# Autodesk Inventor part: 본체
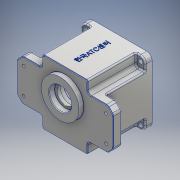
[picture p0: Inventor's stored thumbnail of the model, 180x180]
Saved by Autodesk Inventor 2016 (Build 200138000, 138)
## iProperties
Created: 2017-01
Part Number: 본체
Material: 알루미늄 6061
Document SubType Name: Modeling
Designer: Owner
Mass: 877.062 g
Surface Area: 764.541 cm^2
Volume: 324.838 cm^3
Density: 2.7 g/cm^3
Appearance: 알루미늄 - 평지
Author: Owner
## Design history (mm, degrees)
sketch "스케치3"
  geometry: 1 further point
sketch "스케치4"
  geometry: L1 (-47, -30)-(-47, 30); L2 (47, 30)-(47, -30); L3 (47, -30)-(-47, 30); L4 (-47, -30)-(47, 30); L5 (-33, -47)-(33, -47); L6 (33, 47)-(-33, 47); L7 (-33, -47)-(33, 47); L8 (33, -47)-(-33, 47); L9 (33, -47)-(33, -30); L10 (33, 30)-(33, 47); L11 (-47, 30)-(-33, 30); L12 (33, 30)-(47, 30); L13 (-33, 47)-(-33, 30); L14 (-33, -30)-(-33, -47); L15 (47, -30)-(33, -30); L16 (-33, -30)-(-47, -30); 1 further point
  constraints: 32 end point, 10 parallel, 4 equal length, 4 midpoint, 4 perpendicular, 3 horizontal
  dimensions: "d4" = 60 distance of L1.start L1.end; "d5" = 66 distance of L6.start L6.end; "d6" = 94 distance of L2.end L1.start; "d7" = 94 distance of L6.end L5.start
extrude "돌출2" new body sketch "스케치4" distance "d8" = 80; taper "d9" = 0 deg
sketch "스케치5"
  geometry: L1 (47, 47)-(-47, 47); L2 (-47, 47)-(-47, -47); L3 (-47, -47)-(47, -47); L4 (47, -47)-(47, 47); L5 (47, 47)-(-47, -47); L6 (-47, 47)-(47, -47); 3 further points
  constraints: 12 end point, 2 midpoint, 2 parallel, 1 horizontal, 1 horizontal alignment, 1 perpendicular, 1 vertical alignment
extrude "돌출3" join sketch "스케치5" distance "d10" = 10; taper "d11" = 0 deg
sketch "스케치6"
  geometry: L1 (-62, -30)-(62, -30); L2 (70, -22)-(70, 22); L3 (62, 30)-(-62, 30); L4 (-70, 22)-(-70, -22); L5 (-70, -30)-(70, 30); L6 (70, -30)-(-70, 30); L7 (-62, 30)-(-70, 22); L8 (-70, -22)-(-62, -30); L9 (62, -30)-(70, -22); L10 (62, 30)-(70, 22); 2 further points
  constraints: 20 end point, 8 point on line, 2 midpoint, 2 parallel, 1 horizontal, 1 horizontal alignment, 1 perpendicular
  dimensions: "d12" = 140 distance of L5.end L6.end; "d13" = 8 distance of L3.end L6.end; "d14" = 8 distance of L4.start L6.end (= d13); "d15" = 8 distance of L4.end L5.start (= d13); "d16" = 8 distance of L1.start L5.start (= d15); "d17" = 8 distance of L1.end L6.start (= d13); "d18" = 8 distance of L2.start L6.start (= d17); "d19" = 8 distance of L3.start L5.end (= d13); "d20" = 8 distance of L2.end L5.end (= d19)
extrude "돌출4" join sketch "스케치6" distance "d21" = 13; taper "d22" = 0 deg
sketch "스케치7"
  geometry: C1 r 27.5 at (0, 11); 1 further point
  constraints: 1 centre point, 1 vertical alignment
  dimensions: "d23" = 11 distance of C1.centre point (0, 0); "d24" = 55 diameter of C1
extrude "돌출5" join sketch "스케치7" distance "d25" = 7; taper "d26" = 0 deg
sketch "스케치9"
  geometry: C1 r 43 at (0, 0); 1 further point
  constraints: 1 centre point, 1 coincident
  dimensions: "d33" = 86 diameter of C1
extrude "돌출6" cut sketch "스케치9" distance "d34" = 9; taper "d35" = 0 deg
sketch "스케치10"
  geometry: C1 r 40 at (0, 0); 1 further point
  constraints: 1 centre point, 1 coincident
  dimensions: "d36" = 80 diameter of C1
extrude "돌출7" cut sketch "스케치10" distance "d37" = 62; taper "d38" = 0 deg
sketch "스케치11"
  geometry: C1 r 27.5 at (0, 0) reference; C2 r 16 at (0, 0); 1 further point
  constraints: 1 centre point, 1 coincident
  dimensions: "d39" = 32 diameter of C2
extrude "돌출8" cut sketch "스케치11" distance "d40" = 8; taper "d41" = 0 deg
sketch "스케치12"
  geometry: C1 r 16 at (0, 0) reference; C2 r 12.5 at (0, 0); 1 further point
  constraints: 1 centre point, 1 coincident
  dimensions: "d42" = 25 diameter of C2
extrude "돌출9" cut sketch "스케치12" distance "d43" = 9; taper "d44" = 0 deg
sketch "스케치15"
  geometry: C1 r 12.5 at (0, -11) reference; C2 r 21 at (0, -11); 1 further point
  constraints: 1 centre point, 1 coincident
  dimensions: "d48" = 42 diameter of C2
extrude "돌출11" join sketch "스케치15" distance "d49" = 7; taper "d50" = 0 deg
sketch "스케치16"
  geometry: C1 r 21 at (0, 0) reference; C2 r 17.5 at (0, 0); 1 further point
  constraints: 1 centre point, 1 coincident
  dimensions: "d51" = 35 diameter of C2
extrude "돌출12" cut sketch "스케치16" distance "d52" = 10; taper "d53" = 0 deg
sketch "스케치17"
  geometry: A1 r 36 centre (0, 0) between (35.778, -3.995) and (-34.366, -10.722); A2 r 4 centre (-36, 0) between (-35.852, -3.997) and (-35.852, 3.997); A3 r 4 centre (36, 0) between (35.852, 3.997) and (35.852, -3.997); A4 r 40 centre (0, 0) between (39.148, -8.214) and (39.148, 8.214) reference; A5 r 3.5 centre (35.722, -7.495) between (39.148, -8.214) and (35.778, -3.995); A6 r 3.5 centre (35.722, 7.495) between (35.778, 3.995) and (39.148, 8.214); A7 r 3.5 centre (-35.722, -7.495) between (-35.778, -3.995) and (-39.148, -8.214); A8 r 3.5 centre (-35.722, 7.495) between (-39.148, 8.214) and (-35.778, 3.995); 1 further point
  constraints: 27 point on circle, 8 tangent, 7 centre point, 2 horizontal alignment, 1 coincident
  dimensions: "d54" = 72 diameter of A1; "d55" = 8 diameter of A2; "d56" = 8 diameter of A3; "d57" = 7 diameter of A5; "d58" = 7 diameter of A6; "d59" = 7 diameter of A7; "d60" = 7 diameter of A8
extrude "돌출13" join sketch "스케치17" stored distance "d61" = 7; taper "d62" = 0 deg
sketch "스케치18"
  geometry: A1 r 15 centre (0, 20) between (8.978, 7.984) and (-8.978, 7.984); A2 r 21 centre (0, -11) between (-8.978, 7.984) and (8.978, 7.984) reference; 1 further point
  constraints: 4 point on circle, 1 centre point, 1 vertical alignment
  dimensions: "d63" = 20 distance of A1.centre point (0, 0); "d64" = 30 diameter of A1
extrude "돌출14" join sketch "스케치18" distance "d65" = 7; taper "d66" = 0 deg
sketch "스케치19"
  geometry: C1 r 11 at (0, 20); A1 r 15 centre (0, 20) between (8.978, 7.984) and (-8.978, 7.984) reference; 1 further point
  constraints: 1 centre point, 1 coincident
  dimensions: "d128" = 22 diameter of C1
extrude "돌출15" cut sketch "스케치19" distance "d68" = 7; taper "d69" = 0 deg
sketch "스케치20"
  geometry: C1 r 11 at (0, 0) reference; C2 r 9.5 at (0, 0); 1 further point
  constraints: 1 centre point, 1 coincident
  dimensions: "d70" = 19 diameter of C2
extrude "돌출16" cut sketch "스케치20" distance "d71" = 1; taper "d72" = 0 deg
fillet "모깎기1" dims "d73" = 8
sketch "스케치21"
  geometry: L1 (-40, -40)-(40, -40); L2 (40, -40)-(40, 40); L3 (40, 40)-(-40, 40); L4 (-40, 40)-(-40, -40); L5 (-40, -40)-(40, 40); L6 (40, -40)-(-40, 40); 5 further points
  constraints: 12 end point, 4 coincident, 2 midpoint, 2 parallel, 1 horizontal, 1 perpendicular
  dimensions: "d75" = 80 distance of L2.end L3.end; "d76" = 80 distance of L1.end L2.end
hole "구멍1" sketch "스케치21" at (40, 40), (40, -40), (-40, -40), (-40, 40) diameter "d77" = 7; stored, may be unused: countersink angle "d81" = 90 deg, drill point angle "d83" = 118 deg; dims "d78" = 6, "d79" = 10, "d80" = 4, "d82" = 8
sketch "스케치22"
  geometry: A1 r 4 centre (36, 0) between (35.852, 3.997) and (35.852, -3.997) reference; 2 further points
  constraints: 1 coincident
hole "구멍2" sketch "스케치22" at (36, 0) diameter "d84" = 3.242; stored, may be unused: countersink angle "d88" = 90 deg, drill point angle "d90" = 118 deg; dims "d85" = 7, "d86" = 10, "d87" = 4, "d89" = 9
chamfer "모따기1" distance "d91" = 1; stored, may be unused: second distance "d92" = 2, angle "d93" = 45 deg
fillet "모깎기3" dims "d94" = 0.3
fillet "모깎기4" dims "d95" = 2
fillet "모깎기5" dims "d96" = 0.3
chamfer "모따기2" distance "d97" = 1; stored, may be unused: second distance "d98" = 2, angle "d99" = 45 deg
sketch "스케치23"
  geometry: L1 (-33, -47)-(-33, -30) reference; L2 (33, -47)-(-33, -47) reference; L3 (33, -30)-(33, -47) reference; L4 (33, -30)-(62, -30) reference; L5 (62, -30)-(70, -22) reference; L6 (70, -22)-(70, 22) reference; L7 (70, 22)-(62, 30) reference; L8 (33, 30)-(62, 30) reference; L9 (33, 47)-(33, 30) reference; L10 (-33, 47)-(33, 47) reference; L11 (-33, 30)-(-33, 47) reference; L12 (-33, 30)-(-62, 30) reference; L13 (-62, 30)-(-70, 22) reference; L14 (-70, 22)-(-70, -22) reference; L15 (-70, -22)-(-62, -30) reference; L16 (-33, -30)-(-62, -30) reference; L17 (-61.586, 29)-(-32, 29); L18 (-32, 29)-(-32, 46); L19 (-32, 46)-(32, 46); L20 (32, 46)-(32, 29); L21 (32, 29)-(61.586, 29); L22 (61.586, 29)-(69, 21.586); L23 (69, 21.586)-(69, -21.586); L24 (69, -21.586)-(61.586, -29); L25 (61.586, -29)-(32, -29); L26 (32, -29)-(32, -46); L27 (32, -46)-(-32, -46); L28 (-32, -46)-(-32, -29); L29 (-32, -29)-(-61.586, -29); L30 (-61.586, -29)-(-69, -21.586); L31 (-69, -21.586)-(-69, 21.586); L32 (-69, 21.586)-(-61.586, 29); C1 r 27.8 at (0, 11) reference; 1 further point
  constraints: 32 end point, 15 other
  dimensions: "d100" = 1 distance between parallel lines of L12 L17
extrude "돌출17" cut sketch "스케치23" distance "d101" = 1; taper "d102" = 0 deg
fillet "모깎기6" dims "d103" = 5
fillet "모깎기7" dims "d104" = 5
fillet "모깎기8" dims "d105" = 5
fillet "모깎기9" dims "d106" = 2
fillet "모깎기11" dims "d108" = 2
sketch "스케치24"
  geometry: 2 further points
  dimensions: "d109" = 19 vertical distance of point (0, 0) point (60, -19); "d110" = 60 horizontal distance of point (0, 0) point (60, -19)
hole "구멍3" sketch "스케치24" at (60, -19) diameter "d111" = 4; stored, may be unused: countersink angle "d115" = 90 deg, drill point angle "d117" = 118 deg; dims "d112" = 4, "d113" = 10, "d114" = 4, "d116" = 9
fillet "모깎기13" dims "d119" = 2
fillet "모깎기14" dims "d120" = 2
fillet "모깎기15" dims "d121" = 2
fillet "모깎기16" dims "d122" = 2
fillet "모깎기17" dims "d123" = 3
sketch "스케치25"
  geometry: L1 (0, 0)-(78, 0) reference; 2 further points
  constraints: 1 vertical alignment, 1 other
  dimensions: "d124" = 40 distance from line of point (39, -40) L1
feature "엠보싱1" sketch "스케치25" dims "d125" = 0.5, "d126" = 0
fillet "모깎기18" dims "d127" = 2
node "솔리드2"
mirror "대칭1"
mirror "대칭2"
mirror "대칭3"
node "투영된 루프1"
node "투영된 루프2"
node "투영된 루프4"
node "투영된 루프5"
node "투영된 루프6"
